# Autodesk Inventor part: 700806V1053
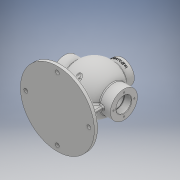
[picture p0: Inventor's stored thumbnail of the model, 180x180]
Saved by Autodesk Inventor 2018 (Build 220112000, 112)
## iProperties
Created: 2020-08
Part Number: 700806V1053
Material: Generic
Document SubType Name: Modeling
Designer: Administrator
Density: 1 g/cm^3
Appearance: Default
Author: Administrator
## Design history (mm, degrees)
sketch "Sketch1"
  geometry: L1 (0, -53)-(0, 53); A1 r 53 centre (0, 0) between (0, 53) and (0, -53); 1 further point
  constraints: 2 end point, 2 point on circle, 1 centre point, 1 coincident
  dimensions: "d0" = 106 diameter of A1
revolve "Revolution1" sketch "Sketch1" stored, may be unused: angle "d1" = 90 deg
sketch "Sketch2"
  geometry: C1 r 27 at (0, 0); 1 further point
  constraints: 1 centre point, 1 coincident
  dimensions: "d2" = 54 diameter of C1
extrude "Extrusion1" join sketch "Sketch2" distance "d3" = 65; taper "d4" = 0 deg
workplane "Work Plane1"
sketch "Sketch3"
  geometry: C1 r 85 at (0, 0); 1 further point
  constraints: 1 centre point, 1 coincident
  dimensions: "d6" = 170 diameter of C1
extrude "Extrusion2" join sketch "Sketch3" distance "d7" = 10; taper "d8" = 0 deg
sketch "Sketch4"
  geometry: C1 r 31 at (0, 0); 1 further point
  constraints: 1 centre point, 1 coincident
  dimensions: "d9" = 62 diameter of C1
extrude "Extrusion3" join sketch "Sketch4" stored distance "d10" = 136; taper "d11" = 0 deg
sketch "Sketch5"
  geometry: L1 (4, 85)-(4, 84.906); L2 (-4, 85)-(-4, 84.906); L3 (-85, 4)-(-84.906, 4); L4 (-85, -4)-(-84.906, -4); L5 (84.906, 4)-(85, 4); L6 (84.906, -4)-(85, -4); L7 (4, -84.906)-(4, -85); L8 (-4, -84.906)-(-4, -85); L9 (52, -67.238)-(52, -85); L10 (73.321, -43)-(85, -43); L11 (-52, -67.238)-(-52, -85); L12 (-85, -43)-(-73.321, -43); L13 (-4, -43)-(4, -43); L14 (52, 85)-(52, 67.238); L15 (52, 4)-(52, -4); L16 (73.321, 43)-(85, 43); L17 (-85, 43)-(-73.321, 43); L18 (-4, 43)-(4, 43); L19 (-52, 85)-(-52, 67.238); L20 (-52, 4)-(-52, -4); L21 (4, 43)-(4, 4); L22 (4, -4)-(4, -43); L23 (-4, 43)-(-4, 4); L24 (-4, -4)-(-4, -43); L25 (-52, 4)-(-4, 4); L26 (4, 4)-(52, 4); L27 (-52, -4)-(-4, -4); L28 (4, -4)-(52, -4); 1 further point
  constraints: 56 end point, 17 other
extrude "Extrusion4" join sketch "Sketch5" stored distance "d20" = 136; taper "d21" = 0 deg
fillet "Fillet1" dims "d22" = 3
fillet "Fillet2" dims "d23" = 3
sketch "Sketch6"
  geometry: C1 r 17.5 at (0, 0); 1 further point
  constraints: 1 centre point, 1 coincident
  dimensions: "d24" = 35 diameter of C1
extrude "Extrusion5" cut sketch "Sketch6" distance "d25" = 16; taper "d26" = 0 deg
sketch "Sketch9"
  geometry: L1 (0, -43)-(0, 43); L2 (-4, 40)-(-4, 7) reference; A1 r 43 centre (0, 0) between (0, 43) and (0, -43); 4 further points; 1 other entity
  constraints: 2 end point, 2 point on circle, 1 centre point, 1 coincident, 1 parallel, 1 other
revolve "Revolution2" sketch "Sketch9" stored, may be unused: angle "d34" = 90 deg
sketch "Sketch10"
  geometry: C1 r 13 at (0, 0); 1 further point
  constraints: 1 centre point, 1 coincident
  dimensions: "d35" = 26 diameter of C1
extrude "Extrusion8" cut sketch "Sketch10" stored distance "d36" = 1.75; taper "d37" = 0 deg
chamfer "Chamfer1" distance "d38" = 1; stored, may be unused: second distance "d39" = 2, angle "d40" = 45 deg
fillet "Fillet3" dims "d41" = 3
sketch "Sketch11"
  geometry: A1 r 72.5 centre (0, 0) between (0, 72.5) and (72.5, 0); 3 further points
  constraints: 4 point on circle, 1 centre point, 1 coincident
  dimensions: "d43" = 145 diameter of A1
hole "Hole1" sketch "Sketch11" at (0, 72.5), (72.5, 0), (-72.5, 0), (0, -72.5) diameter "d44" = 9; stored, may be unused: countersink angle "d48" = 90 deg, drill point angle "d50" = 118 deg; dims "d45" = 6, "d46" = 4, "d47" = 2, "d49" = 8
sketch "Sketch12"
  geometry: A1 r 24 centre (0, 0) between (0, 24) and (-24, 0); 3 further points
  constraints: 4 point on circle, 1 centre point, 1 coincident
  dimensions: "d51" = 48 diameter of A1
hole "Hole2" sketch "Sketch12" at (0, 24), (-24, 0), (24, 0), (0, -24) diameter "d52" = 3.242; stored, may be unused: countersink angle "d56" = 90 deg, drill point angle "d58" = 118 deg; dims "d53" = 12, "d54" = 4, "d55" = 2, "d57" = 15
mirror "Mirror1"
sketch "Sketch13"
  geometry: A1 r 20 centre (0, 0) between (-20, 0) and (0, 20); 3 further points
  constraints: 4 point on circle, 1 centre point, 1 coincident
  dimensions: "d59" = 40 diameter of A1
hole "Hole3" sketch "Sketch13" at (-20, 0), (0, 20), (20, 0), (0, -20) diameter "d60" = 3.242; stored, may be unused: countersink angle "d64" = 90 deg, drill point angle "d66" = 118 deg; dims "d61" = 12, "d62" = 4, "d63" = 2, "d65" = 15
workplane "Work Plane2"
sketch "Sketch14"
  geometry: L1 (0, 47.286)-(0, 65); L2 (27, 47.286)-(27, 65) reference; L3 (-27.233, 56)-(27, 56); L4 (-20.856, 59.002)-(20.623, 59.002); L5 (20.623, 59.002)-(20.623, 52.998); L6 (20.623, 52.998)-(-20.856, 52.998); L7 (-20.856, 52.998)-(-20.856, 59.002); L8 (-93.742, 96.348)-(-52.263, 96.348); 3 further points
  constraints: 6 end point, 2 midpoint, 2 other
emboss "Emboss1" sketch "Sketch14" dims "d69" = 0.5, "d70" = 0
sketch "Sketch15"
  geometry: C1 r 17.5 at (0, 0); 1 further point
  constraints: 1 centre point, 1 coincident
  dimensions: "d71" = 35 diameter of C1
extrude "Extrusion9" cut sketch "Sketch15" distance "d72" = 16; taper "d73" = 0 deg
sketch "Sketch16"
  geometry: C1 r 18.5 at (0, 0); 1 further point
  constraints: 1 centre point, 1 coincident
  dimensions: "d74" = 37 diameter of C1
extrude "Extrusion10" cut sketch "Sketch16" distance "d75" = 1.75; taper "d76" = 0 deg
sketch "Sketch17"
  geometry: C1 r 17.5 at (0, 0); 1 further point
  constraints: 1 centre point, 1 coincident
  dimensions: "d77" = 35 diameter of C1
extrude "Extrusion11" cut sketch "Sketch17" extent not by distance; stored distance "d78" = 1.75; taper "d79" = 0 deg
chamfer "Chamfer2" distance "d80" = 1; stored, may be unused: second distance "d81" = 2, angle "d82" = 45 deg
body "Solid1"
other parameters: "d5" = -85, "d12" = 4, "d13" = 4, "d14" = 4, "d15" = 4, "d16" = 52, "d17" = 52, "d18" = 43, "d19" = 43
